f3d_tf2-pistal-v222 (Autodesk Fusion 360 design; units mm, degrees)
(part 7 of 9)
sketch "Sketch141" plane through (-0.0003, 0, 0) normal (-1, 0, 0) x axis (0, -1, 0)
  curve K1 (-134.7944, -30.1716) -> (-146.1998, -63.1046)
  curve K2 (-135.347, -29.366) -> (-134.7944, -30.1716)
  curve K3 (-136.1286, -29.6952) -> (-135.347, -29.366)
  line L1 (-136.7565, -29.9764) -> (-136.1286, -29.6952)
  line L2 (-136.8552, -29.6952) -> (-136.7565, -29.9764)
  line L3 (-144.3129, -29.6952) -> (-136.8552, -29.6952)
  line L4 (-159.3646, -64.9915) -> (-144.3129, -29.6952)
  line L5 (-144.2618, -68.8977) -> (-159.3646, -64.9915)
  curve K4 (-143.2922, -67.2348) -> (-144.2618, -68.8977)
  curve K5 (-143.2922, -67.2348) -> (-146.2332, -63.1316)
  line L6 (-147.5, -52.5) -> (-140.5, -52.5)
  line L7 (-147.5, -45.5) -> (-147.5, -52.5)
  line L8 (-140.5, -45.5) -> (-147.5, -45.5)
  line L9 (-140.5, -52.5) -> (-140.5, -45.5)
  line L10 (-147.5, -45.5) -> (-140.5, -52.5)
  line L11 (-140.5, -45.5) -> (-147.5, -52.5)
  arc A1 centre (-147.1582, -61.9508) radius 1.5 clockwise from (-146.1998, -63.1046) to (-146.2332, -63.1316)
  point P18 (-144, -49)
  point P16 (-147.5, -45.5)
  point P17 (-140.5, -45.5)
  point P15 (-147.5, -52.5)
  horizontal L6
  perpendicular L6 L7
  parallel L6 L8
  parallel L7 L9
  coincident L10 P18
  coincident L11 P18
  dimension "d1160" distance P16 P17 = 7
  dimension "d1161" distance P15 P16 = 7
extrude "Extrude141" add sketch "Sketch141" profile of L6 L7 L8 L9 along normal blind 4
combine "Combine131"
move_face "MoveFace228"
move_face "MoveFace229"
move_face "MoveFace230"
move_face "MoveFace231"
move_face "MoveFace232"
chamfer "Chamfer75" distance 0.4
move_face "MoveFace233"
move_face "MoveFace234"
sketch "Sketch142" plane through (13, 0, 0) normal (-1, 0, 0) x axis (0, -1, 0)
  line L1 (-223.8866, 10) -> (-223.8866, 17)
  line L2 (-215.8866, 10) -> (-223.8866, 10)
  line L3 (-227, -22) -> (-227, -14.8472)
  line L4 (-167.4832, -22) -> (-227, -22)
  line L5 (-157.3502, 10) -> (-167.4832, -22)
  line L6 (-157.3502, 17) -> (-157.3502, 10)
  line L7 (-223.8866, 17) -> (-157.3502, 17)
  arc A1 centre (-185.5, -18.5) radius 41.6604 clockwise from (-227, -14.8472) to (-215.8866, 10)
  circle C1 centre (-185.5706, -18.2123) radius 2.5
  arc A2 centre (-162.3398, -25.3102) radius 12.267 clockwise from (-154.6681, -15.7382) to (-155.8322, -35.7087)
  circle C2 centre (-162.3398, -25.3102) radius 19.545
  concentric A2 C2
extrude "Extrude142" new body sketch "Sketch142" profile of L4 L5 C2 against normal blind 5.398
mirror "Mirror33" mirrorStitchTolerance 0.1
combine "Combine132"
combine "Combine133"
move_face "MoveFace235"
fillet "Fillet164" radius 3.5
move_face "MoveFace236"
fillet "Fillet165" radius 3.5
extrude "Extrude143" cut of existing geometry blind -18
extrude "Extrude144" cut of existing geometry blind -29
offset_faces "OffsetFaces17" distance 0.8
sketch "Sketch143" plane through (-18.0019, 0, 0) normal (-1, 0, 0) x axis (0, -1, 0)
  line L1 (-163.0153, -60.3193) -> (-143.9303, -157.3483)
  line L2 (-163.931, -57.8793) -> (-163.0153, -60.3193)
  curve K1 (-163.8476, -56.0881) -> (-163.931, -57.8793)
  curve K2 (-163.8476, -56.0881) -> (-157.7262, -38.8106)
  curve K3 (-155.8322, -35.7087) -> (-157.7262, -38.8106)
  line L3 (-200.2987, -133.9094) -> (-171.9916, -32.8813)
  arc A1 centre (-162.3398, -25.3102) radius 133.3153 clockwise from (-143.9303, -157.3483) to (-186.1858, -156.4755)
  arc A2 centre (-162.3398, -25.3102) radius 12.267 clockwise from (-171.9916, -32.8813) to (-155.8322, -35.7087)
  arc A3 centre (-182.9662, -138.7658) radius 18 clockwise from (-186.1858, -156.4755) to (-200.2987, -133.9094)
  circle C1 centre (-162.4377, -25.1855) radius 2.7
extrude "Extrude145" cut sketch "Sketch143" profile of C1 against normal blind 4
sketch "Sketch144" plane through (17.9981, 0, 0) normal (1, 0, 0) x axis (0, 1, 0)
  line L1 (153.0202, 9.7517) -> (162.2233, -13.0438)
  line L2 (154.6681, -15.7382) -> (153.0202, 9.7517)
  curve K1 (155.8322, -35.7087) -> (163.931, -57.8793)
  line L3 (163.0153, -60.3193) -> (163.931, -57.8793)
  line L4 (143.9303, -157.3483) -> (163.0153, -60.3193)
  line L5 (171.9916, -32.8813) -> (200.2987, -133.9094)
  arc A1 centre (162.3398, -25.3102) radius 12.267 clockwise from (155.8322, -35.7087) to (154.6681, -15.7382)
  arc A2 centre (162.3398, -25.3102) radius 133.3153 clockwise from (186.1858, -156.4755) to (143.9303, -157.3483)
  arc A3 centre (182.9662, -138.7658) radius 18 clockwise from (200.2987, -133.9094) to (186.1858, -156.4755)
  arc A4 centre (162.3398, -25.3102) radius 12.267 clockwise from (162.2233, -13.0438) to (171.9916, -32.8813)
  circle C1 centre (162.4377, -25.1855) radius 2.7
extrude "Extrude146" cut sketch "Sketch144" profile of C1 against normal blind 4
sketch "Sketch145" plane through (13.9981, 0, 0) normal (1, 0, 0) x axis (0, 1, 0)
  circle C1 centre (162.4377, -25.1855) radius 2.7
  circle C2 centre (162.4377, -25.1855) radius 2.5
  concentric C1 C2
  dimension "d1182" diameter C2 = 5
extrude "Extrude147" new body sketch "Sketch145" profile of C2 along normal blind 8 bodies "Trigger pin 1"
mirror "Mirror34" mirrorStitchTolerance 0.1 bodies "Trigger pin 2"
sketch "Sketch146" plane through (0, 0, 0) normal (-1, 0, 0) x axis (0, -1, 0)
  line L1 (-221.138, -55.0188) -> (-226.6232, -53.5432)
  line L2 (-220.3025, -51.9132) -> (-221.138, -55.0188)
  line L3 (-219.9103, -50.4552) -> (-220.3025, -51.9132)
  line L4 (-221, -47) -> (-219.9103, -50.4552)
  line L5 (-228.6991, -19.812) -> (-221, -47)
  line L6 (-249.5886, -19.812) -> (-228.6991, -19.812)
  line L7 (-235.4799, -32.5465) -> (-249.5886, -19.812)
  line L8 (-232.2172, -48.7291) -> (-232.2172, -34.9278)
  curve K1 (-233.7172, -53.9969) -> (-232.2172, -48.7291)
  curve K2 (-234.0863, -54.5504) -> (-233.7172, -53.9969)
  curve K3 (-274.1373, -137.1288) -> (-234.0863, -54.5504)
  line L9 (-262.8717, -140.8736) -> (-274.1373, -137.1288)
  line L10 (-259.7804, -131.5739) -> (-262.8717, -140.8736)
  line L11 (-243.214, -137.0808) -> (-259.7804, -131.5739)
  line L12 (-225.7243, -72.0674) -> (-243.214, -137.0808)
  line L13 (-225.1962, -70.1041) -> (-225.7243, -72.0674)
  line L14 (-230.9458, -56.7232) -> (-225.1962, -70.1041)
  line L15 (-228.7303, -48.4876) -> (-230.9458, -56.7232)
  line L16 (-225.4972, -49.3573) -> (-228.7303, -48.4876)
  line L17 (-226.6232, -53.5432) -> (-225.4972, -49.3573)
  line L18 (-248.9379, -95.078) -> (-240, -75)
  line L19 (-240, -99.0568) -> (-248.9379, -95.078)
  line L20 (-231.8266, -74.6064) -> (-242.2626, -98.0496)
  line L21 (-233.3246, -77.9716) -> (-240, -75)
  line L22 (-271.4894, -85.039) -> (-248.9379, -95.078)
  line L23 (-259.8634, -66.1576) -> (-240, -75)
  arc A1 centre (-222.4144, -18.0709) radius 19.5 clockwise from (-232.2172, -34.9278) to (-235.4799, -32.5465)
  point P27 (-242.2626, -98.0496)
  point P29 (-233.3246, -77.9716)
  perpendicular L18 L19
  coincident L19 P27
  perpendicular L19 L20
  coincident L20 P29
  perpendicular L20 L21
  perpendicular L18 L22
  perpendicular L18 L23
extrude "Extrude148" new body sketch "Sketch146" profile of K3 L18 L22 L23 along normal blind 5
extrude "Extrude149" new body sketch "Sketch146" profile of L18 L19 L20 L21 against normal blind 5
combine "Combine134"
combine "Combine135"
combine "Combine136"
combine "Combine137"
move_face "MoveFace237"
move_face "MoveFace238"
delete_face "DeleteFace132"
move_face "MoveFace239"
move_face "MoveFace240"
move_face "MoveFace241"
move_face "MoveFace242"
move_face "MoveFace243"
move_face "MoveFace244"
move_face "MoveFace245"
sketch "Sketch147" plane through (0, 172.4408, 76.7638) normal (0, 0.9136, 0.4067) x axis (-1, 0, 0)
  line L1 (5, -166.1219) -> (5, -180.0994)
  line L2 (0, -166.1219) -> (5, -166.1219)
  line L3 (0, -166.3219) -> (0, -166.1219)
  line L4 (-4.8, -166.3219) -> (0, -166.3219)
  line L5 (-4.8, -179.8994) -> (-4.8, -166.3219)
  line L6 (0, -179.8994) -> (-4.8, -179.8994)
  line L7 (0, -180.0994) -> (0, -179.8994)
  line L8 (5, -180.0994) -> (0, -180.0994)
  circle C1 centre (0, -173) radius 1.55
  dimension "d1191" diameter C1 = 3.1
extrude "Extrude150" cut sketch "Sketch147" profile of C1 along normal blind 11 and against normal blind 4
sketch "Sketch148" plane through (0, 172.6236, 76.8451) normal (0, -0.9136, -0.4067) x axis (1, 0, 0)
  line L1 (5, -166.1219) -> (5, -180.0994)
  line L2 (0, -166.1219) -> (5, -166.1219)
  line L3 (0, -166.3219) -> (0, -166.1219)
  line L4 (-5, -166.3219) -> (0, -166.3219)
  line L5 (-5, -179.8994) -> (-5, -166.3219)
  line L6 (0, -179.8994) -> (-5, -179.8994)
  line L7 (0, -180.0994) -> (0, -179.8994)
  line L8 (5, -180.0994) -> (0, -180.0994)
  circle C1 centre (0, -173) radius 1.55
  circle C2 centre (0, -173) radius 3.1
  concentric C1 C2
  dimension "d1196" diameter C2 = 6.2
extrude "Extrude151" cut sketch "Sketch148" profile of C1 C2 blind -6 from offset -4
chamfer "Chamfer76" distance 1.4
move_face "MoveFace246"
sketch "Sketch149" plane through (-21.9977, 0, 0) normal (-1, 0, 0) x axis (0, -1, 0)
  line L1 (-251.5226, -138.0193) -> (-252.4999, -140.9593)
  line L2 (-250.6312, -137.5727) -> (-251.5226, -138.0193)
  line L3 (-246.3705, -138.989) -> (-250.6312, -137.5727)
  line L4 (-245.9238, -139.8804) -> (-246.3705, -138.989)
  line L5 (-246.9532, -142.977) -> (-245.9238, -139.8804)
  line L6 (-202.4935, -157.7558) -> (-246.9532, -142.977)
  line L7 (-197.128, -152.3541) -> (-198.032, -155.4234)
  line L8 (-197.128, -141.3784) -> (-197.128, -152.3541)
  line L9 (-157.1727, -23.4112) -> (-197.128, -141.3784)
  line L10 (-181.4232, -15.4864) -> (-162.8556, -15.4864)
  line L11 (-182.8566, -22.0495) -> (-181.4232, -15.4864)
  line L12 (-220.8838, -26.6905) -> (-188.6207, -26.6905)
  line L13 (-220.8838, -56.1363) -> (-220.8838, -26.6905)
  line L14 (-253.6825, -136.8114) -> (-220.8838, -56.1363)
  line L15 (-223, -24) -> (-222.607, -35.9739)
  line L16 (-212.2901, -25.397) -> (-223, -24)
  circle C1 centre (-162.4377, -25.1855) radius 2.7
  circle C2 centre (-210.9636, -95.9994) radius 18.6716
  arc A1 centre (-201.3894, -154.4345) radius 3.5 clockwise from (-198.032, -155.4234) to (-202.4935, -157.7558)
  arc A2 centre (-162.8556, -21.4864) radius 6 clockwise from (-162.8556, -15.4864) to (-157.1727, -23.4112)
  arc A3 centre (-188.6207, -20.7905) radius 5.9 clockwise from (-182.8566, -22.0495) to (-188.6207, -26.6905)
  arc A4 centre (-250.4402, -138.1296) radius 3.5 clockwise from (-252.4999, -140.9593) to (-253.6825, -136.8114)
  arc A5 centre (-212, -36) radius 10.607 clockwise from (-222.607, -35.9739) to (-212.2901, -25.397)
extrude "Extrude152" cut sketch "Sketch149" profile of L12 L13 A5 L15 L16 against normal blind 2
fillet "Fillet166" radius 0.7
move_face "MoveFace247"
sketch "Sketch150" plane through (-19.9977, 0, 0) normal (-1, 0, 0) x axis (0, -1, 0)
  line L1 (-246.6184, -139.2754) -> (-250.604, -137.9506)
  line L2 (-246.3017, -139.9076) -> (-246.6184, -139.2754)
  line L3 (-247.6265, -143.8932) -> (-246.3017, -139.9076)
  line L4 (-248.2587, -144.2099) -> (-247.6265, -143.8932)
  line L5 (-252.2443, -142.8851) -> (-248.2587, -144.2099)
  line L6 (-252.5611, -142.2529) -> (-252.2443, -142.8851)
  line L7 (-251.2362, -138.2673) -> (-252.5611, -142.2529)
  line L8 (-250.604, -137.9506) -> (-251.2362, -138.2673)
  line L9 (-153.2868, -55.2709) -> (-155.774, -64.8873)
  curve K1 (-153.2868, -55.2709) -> (-153.3896, -51.2349)
  line L10 (-153.3078, -51.0336) -> (-153.3896, -51.2349)
  line L11 (-209.4603, -30.1452) -> (-144.1511, -30.1452)
  curve K2 (-209.4603, -30.1452) -> (-209.6429, -30.1443)
  line L12 (-255.6377, -143.2782) -> (-209.6429, -30.1443)
  line L13 (-209.1721, -158.7239) -> (-255.6377, -143.2782)
  line L14 (-185.0159, -86.0541) -> (-209.1721, -158.7239)
  line L15 (-158.6388, -64.1463) -> (-159.119, -65.3274)
  line L16 (-155.774, -64.8873) -> (-158.6388, -64.1463)
  arc A1 centre (-116.7403, -54.6121) radius 36.7422 clockwise from (-153.3078, -51.0336) to (-144.1511, -30.1452)
  arc A2 centre (-156.0731, -95.675) radius 30.5 clockwise from (-185.0159, -86.0541) to (-159.119, -65.3274)
  circle C1 centre (-205, -40) radius 2.6
  dimension "d1205" diameter C1 = 5.2
extrude "Extrude153" new body sketch "Sketch150" profile of C1 along normal blind 4 and against normal blind 4 bodies "5mm pin_3"
combine "Combine138"
remove_body "RemoveBody80"
combine "Combine139"
combine "Combine140"
mirror "Mirror35" mirrorStitchTolerance 0.1 bodies "5mm pin_4"
combine "Combine141"
combine "Combine142"
mirror "Mirror36" mirrorStitchTolerance 0.1 bodies "Grip plate_L"
offset_faces "OffsetFaces18" distance -0.1
offset_faces "OffsetFaces19" distance -0.1
move_face "MoveFace248"
move_face "MoveFace249"
delete_face "DeleteFace133"
delete_face "DeleteFace134"
move_face "MoveFace250" TranslateX 0 TranslateY 0.5 TranslateZ 0
sketch "Sketch151" plane through (0, 70.058, 0) normal (0, 1, 0) x axis (-1, 0, 0)
  line L1 (8.4524, 1) -> (8.4524, 26)
  line L2 (15.2981, 1) -> (8.4524, 1)
  line L3 (15.2981, -14.4738) -> (15.2981, 1)
  line L4 (-7.5981, -22.1738) -> (7.5981, -22.1738)
  line L5 (-15.2981, 1) -> (-15.2981, -14.4738)
  line L6 (-8.4524, 1) -> (-15.2981, 1)
  line L7 (-8.4524, 26) -> (-8.4524, 1)
  line L8 (8.4524, 26) -> (-8.4524, 26)
  line L9 (-1.9977, 30) -> (1.9973, 30)
  line L10 (-17.9977, 14) -> (-19.6612, 14)
  line L11 (-17.9977, 10) -> (-17.9977, 14)
  line L12 (-18.3981, 10) -> (-17.9977, 10)
  line L13 (-18.3981, 1) -> (-18.3981, 10)
  line L14 (-15.4981, 1) -> (-18.3981, 1)
  line L15 (-15.4981, -24.564) -> (-15.4981, 1)
  line L16 (-15.4981, -24.564) -> (15.4981, -24.564)
  line L17 (15.4981, 1) -> (15.4981, -24.564)
  line L18 (18.3981, 1) -> (15.4981, 1)
  line L19 (18.3981, 10) -> (18.3981, 1)
  line L20 (17.9977, 10) -> (18.3981, 10)
  line L21 (17.9977, 14) -> (17.9977, 10)
  line L22 (19.6609, 14) -> (17.9977, 14)
  line L23 (-12.5, -22.064) -> (-17.5, -22.064)
  line L24 (-12.5, -27) -> (-12.5, -22.064)
  line L25 (-17.5, -27) -> (-12.5, -27)
  line L26 (-17.5, -22.064) -> (-17.5, -27)
  circle C1 centre (15.0846, 20.3468) radius 2
  circle C2 centre (-15.0846, 20.3468) radius 2
  arc A1 centre (7.5981, -14.4738) radius 7.7 clockwise from (15.2981, -14.4738) to (7.5981, -22.1738)
  arc A2 centre (-7.5981, -14.4738) radius 7.7 clockwise from (-7.5981, -22.1738) to (-15.2981, -14.4738)
  arc A3 centre (19.6609, 14.2) radius 0.2 clockwise from (19.8593, 14.2247) to (19.6609, 14)
  arc A4 centre (1.9973, 12) radius 18 clockwise from (1.9973, 30) to (19.8593, 14.2247)
  arc A5 centre (-1.9977, 12) radius 18 clockwise from (-19.8597, 14.2247) to (-1.9977, 30)
  arc A6 centre (-19.6612, 14.2) radius 0.2 clockwise from (-19.6612, 14) to (-19.8597, 14.2247)
  circle C3 centre (-15, -22.064) radius 2.5
  point P39 (-17.5, -22.064)
  tangent L16 C3
  horizontal L23
  vertical L24
  horizontal L25
  vertical L26
  coincident C3 P39
  dimension "d1219" diameter C3 = 5
extrude "Extrude154" new body sketch "Sketch151" profile of L15 L16 C3 L23 L24 L25 L26 along normal blind 2 and against normal blind 0
sweep "Sweep1" TwistAngle 0 TaperAngle 0
combine "Combine143"
mirror "Mirror37" mirrorStitchTolerance 0.1
move "Move87" TranslateX 10 TranslateY 0 TranslateZ 0
move "Move88" TranslateX -12 TranslateY 0 TranslateZ 0
move "Move89" TranslateX 2.5 TranslateY 0 TranslateZ 0
move "Move90" TranslateX -0.5 TranslateY 0 TranslateZ 0
move "Move91" TranslateX 0 TranslateY 0.5 TranslateZ 0.5
move "Move92" TranslateX 0 TranslateY 0 TranslateZ -0.5
combine "Combine144"
fillet "Fillet167" radius 0.5
sketch "Sketch152" plane through (19.9977, 0, 0) normal (1, 0, 0) x axis (0, 1, 0)
  line L1 (34.1807, 10) -> (104.3129, 10)
  line L2 (21.5097, 10) -> (34.1807, 10)
  line L3 (21.5097, -1.9634) -> (21.5097, 10)
  curve K1 (21.5097, -1.9634) -> (21.9053, -3.4061)
  curve K2 (21.9053, -3.4061) -> (75.0239, -22.5858)
  line L4 (104.3129, -22.5858) -> (75.0239, -22.5858)
  line L5 (104.3129, 10) -> (104.3129, -22.5858)
  line L6 (13, -4) -> (21, -14)
  line L7 (9, -9) -> (13, -4)
  line L8 (15.5914, -17.2392) -> (9, -9)
  line L9 (21, -14) -> (15.5914, -17.2392)
  parallel L6 L8
extrude "Extrude155" new body sketch "Sketch152" profile of L6 L7 L8 L9 against normal blind 15
sketch "Sketch153" plane through (0, 5.9756, 4.7805) normal (0, 0.7809, 0.6247) x axis (-1, 0, 0)
  line L1 (-19.9977, -24.0508) -> (-19.9977, -11.2445)
  line L2 (-4.9977, -24.0508) -> (-19.9977, -24.0508)
  line L3 (-4.9977, -11.2445) -> (-4.9977, -24.0508)
  line L4 (-19.9977, -11.2445) -> (-4.9977, -11.2445)
  circle C1 centre (0, -24) radius 6
extrude "Extrude156" cut sketch "Sketch153" profile of L2 L3 C1 along normal blind 10
fillet "Fillet168" radius 0.5
sketch "Sketch154" plane through (0, 13.7843, 11.0274) normal (0, -0.7809, -0.6247) x axis (1, 0, 0)
  line L1 (-0.9759, -22.8753) -> (-0.971, -22.9146)
  curve K1 (-0.971, -22.9146) -> (-0.789, -24.1633)
  curve K2 (-0.789, -24.1633) -> (0, -28.7793)
  curve K3 (0, -28.7793) -> (0.789, -24.1633)
  curve K4 (0.789, -24.1634) -> (0.971, -22.9146)
  line L2 (0.971, -22.9146) -> (0.9759, -22.8753)
  curve K5 (0.9759, -22.8753) -> (4.0241, -22.8753)
  line L3 (4.0241, -22.8753) -> (4.029, -22.9146)
  curve K6 (4.029, -22.9146) -> (4.211, -24.1633)
  curve K7 (4.211, -24.1633) -> (4.8061, -27.5918)
  curve K8 (-4.8061, -27.5918) -> (-4.211, -24.1634)
  curve K9 (-4.211, -24.1634) -> (-4.029, -22.9146)
  line L4 (-4.029, -22.9146) -> (-4.0241, -22.8753)
  curve K10 (-4.0241, -22.8753) -> (-0.9759, -22.8753)
  arc A1 centre (0, -24) radius 6 clockwise from (-4.8061, -27.5918) to (4.8061, -27.5918)
  circle C1 centre (0, -24) radius 1.75
  concentric A1 C1
  dimension "d1258" diameter C1 = 3.5
extrude "Extrude157" cut sketch "Sketch154" profile of L1 K1 K2 K3 K4 L2 K5 K10 C1 against normal blind 6
fillet "Fillet169" radius 0.5
remove_body "RemoveBody81"
offset_faces "OffsetFaces20" distance 0.1
offset_faces "OffsetFaces21" distance 0.05
offset_faces "OffsetFaces22" distance 0.05
offset_faces "OffsetFaces23" distance 0.05
fillet "Fillet170" radius 0.5
sketch "Sketch155" plane through (0, 18.4695, 14.7756) normal (0, -0.7809, -0.6247) x axis (1, 0, 0)
  circle C1 centre (0, -24) radius 1.75
  circle C2 centre (0, -24) radius 1.4
  concentric C1 C2
  dimension "d1269" diameter C2 = 2.8
extrude "Extrude158" add sketch "Sketch155" along normal blind 6
chamfer "Chamfer77" distance 0.3
offset_faces "OffsetFaces24" distance -0.1
offset_faces "OffsetFaces25" distance -0.1
sketch "Sketch156" plane through (17.9981, 0, 0) normal (1, 0, 0) x axis (0, 1, 0)
  line L1 (153.0202, 9.7517) -> (162.2233, -13.0438)
  line L2 (154.6681, -15.7382) -> (153.0202, 9.7517)
  curve K1 (155.8322, -35.7087) -> (163.931, -57.8793)
  line L3 (163.0153, -60.3193) -> (163.931, -57.8793)
  line L4 (143.9303, -157.3483) -> (163.0153, -60.3193)
  line L5 (171.9916, -32.8813) -> (200.2987, -133.9094)
  line L6 (149.2123, -50.8939) -> (147, -52)
  line L7 (191.6889, -41.9084) -> (149.2123, -50.8939)
  line L8 (201, -46) -> (149, -57)
  line L9 (165.0095, -53.6134) -> (165.0095, -47.5521)
  line L10 (175, -51.5) -> (171.7876, -46.1183)
  line L11 (165.2595, -53.5605) -> (165.2595, -47.4992)
  line L12 (174.7415, -51.5547) -> (171.5291, -46.173)
  line L13 (182.7307, -44.059) -> (150.4604, -50.8854)
  line L14 (151.6826, -50.6268) -> (151.6309, -50.3822)
  line L15 (181.5745, -44.3035) -> (181.5227, -44.059)
  line L16 (160.5395, -54.3034) -> (160.2764, -54.3034)
  line L17 (182.4377, -49.6711) -> (160.5395, -54.3034)
  line L18 (161.3682, -54.3836) -> (161.3165, -54.1391)
  line L19 (181.323, -50.1624) -> (181.2713, -49.9179)
  circle C1 centre (162.4377, -25.1855) radius 2.7
  arc A1 centre (162.3398, -25.3102) radius 12.267 clockwise from (155.8322, -35.7087) to (154.6681, -15.7382)
  arc A2 centre (162.3398, -25.3102) radius 133.3153 clockwise from (186.1858, -156.4755) to (143.9303, -157.3483)
  arc A3 centre (182.9662, -138.7658) radius 18 clockwise from (200.2987, -133.9094) to (186.1858, -156.4755)
  arc A4 centre (162.3398, -25.3102) radius 12.267 clockwise from (162.2233, -13.0438) to (171.9916, -32.8813)
  point P20 (165.0095, -47.5521)
  point P21 (165.0095, -53.6134)
  point P22 (171.7876, -46.1183)
  point P23 (175, -51.5)
  point P24 (165.2595, -47.4992)
  point P25 (165.2595, -53.5605)
  point P26 (171.5291, -46.173)
  point P27 (174.7415, -51.5547)
  point P30 (151.6309, -50.3822)
  point P31 (151.6826, -50.6268)
  point P32 (181.5227, -44.059)
  point P33 (181.5745, -44.3035)
  point P37 (161.3165, -54.1391)
  point P38 (161.3682, -54.3836)
  point P39 (181.2713, -49.9179)
  point P40 (181.323, -50.1624)
  parallel L7 L8
  coincident L7 P20
  coincident L8 P21
  vertical L9
  coincident L7 P22
  midpoint L8 P23
  coincident L7 P24
  coincident L8 P25
  vertical L11
  coincident L7 P26
  coincident L8 P27
  parallel L7 L13
  parallel L10 L12
  coincident L7 P30
  coincident L13 P31
  perpendicular L13 L14
  coincident L7 P32
  coincident L13 P33
  perpendicular L13 L15
  perpendicular L9 L16
  parallel L8 L17
  coincident L17 P37
  coincident L8 P38
  perpendicular L8 L18
  coincident L17 P39
  coincident L8 P40
  perpendicular L8 L19
  dimension "d1275" distance L7 L13 = 0.25
  dimension "d1276" distance L9 L11 = 0.25
  dimension "d1277" distance L10 L12 = 0.25
  dimension "d1283" distance L8 L17 = 0.25
sketch "Sketch157" plane through (17.9981, 0, 0) normal (1, 0, 0) x axis (0, 1, 0)
  line L1 (156.0354, -13.7107) -> (151.0894, -15.2814)
  line L2 (157.9379, -19.7019) -> (156.0354, -13.7107)
  line L3 (161.5785, -18.5458) -> (157.9379, -19.7019)
  line L4 (159.6732, -12.5461) -> (161.5785, -18.5458)
  line L5 (166.5717, -10.3554) -> (159.6732, -12.5461)
  line L6 (166.6474, -10.5937) -> (166.5717, -10.3554)
  line L7 (159.9872, -12.7087) -> (166.6474, -10.5937)
  line L8 (161.8924, -18.7084) -> (159.9872, -12.7087)
  line L9 (157.7753, -20.0158) -> (161.8924, -18.7084)
  line L10 (155.8727, -14.0247) -> (157.7753, -20.0158)
  line L11 (147.3025, -16.7463) -> (155.8727, -14.0247)
  line L12 (151.165, -15.5197) -> (151.0894, -15.2814)
  point P14 (151.165, -15.5197)
  perpendicular L1 L2
  perpendicular L2 L3
  perpendicular L3 L4
  perpendicular L4 L5
  perpendicular L5 L6
  perpendicular L6 L7
  perpendicular L7 L8
  perpendicular L8 L9
  perpendicular L9 L10
  perpendicular L10 L11
  coincident L11 P14
  perpendicular L11 L12
  dimension "d1278" distance L1 L11 = 0.25
  dimension "d1279" distance L2 L10 = 0.25
  dimension "d1280" distance L3 L9 = 0.25
  dimension "d1281" distance L4 L8 = 0.25
  dimension "d1282" distance L5 L7 = 0.25
extrude "Extrude159" cut sketch "Sketch157" + "Sketch156" profile of S2:K1 S2:L5 S2:L7 S2:L8 S2:L9 S2:L10 S2:L11 S2:L12 S2:L13 S1:L1 S1:L2 S1:L3 S1:L4 S1:L5 S1:L6 S1:L7 S1:L8 S1:L9 S1:L10 S1:L11 S1:L12 S2:L14 S2:L15 S2:L17 blind -5 bodies "Trigger_Gear_L", "Trigger(OG)"
split "Split54" bodies "Trigger"
mirror "Mirror38" mirrorStitchTolerance 0.1 bodies "Trigger_Pic_R", "Trigger_Gear_R", "Trigger (2) (1) (1)"
combine "Combine145" bodies "Trigger (2) (1) (1)"
sketch "Sketch158" plane through (0, 0.595, -10.1995) normal (0, -0.0582, 0.9983) x axis (1, 0, 0)
  line L1 (8.0049, 214.6381) -> (-8.0049, 214.6381)
  line L2 (8.0049, 227.9303) -> (8.0049, 214.6381)
  line L3 (8.0049, 227.9303) -> (-8.0049, 227.9303)
  line L4 (-8.0049, 214.6381) -> (-8.0049, 227.9303)
  circle C1 centre (0, 221.2842) radius 2.5
  dimension "d1288" diameter C1 = 5
extrude "Extrude160" cut sketch "Sketch158" profile of C1 against normal blind 4.947
sketch "Sketch159" plane through (0, 0, -10.9038) normal (0, 0, 1) x axis (-1, 0, 0)
  line L1 (0, -220.9739) -> (0, -247.6613)
  line L2 (-8.7952, -220.9739) -> (0, -220.9739)
  line L3 (-8.7952, -243.8316) -> (-8.7952, -220.9739)
  line L4 (-17.6329, -243.8316) -> (-8.7952, -243.8316)
  line L5 (-20.9977, -226.9157) -> (-17.6329, -243.8316)
  line L6 (-20.9977, -189.3316) -> (-20.9977, -226.9157)
  line L7 (-23.9972, -189.3316) -> (-20.9977, -189.3316)
  line L8 (-23.9972, -223.6753) -> (-23.9972, -189.3316)
  line L9 (-19.2261, -247.6613) -> (-23.9972, -223.6753)
  line L10 (0, -247.6613) -> (-19.2261, -247.6613)
  circle C1 centre (-4, -222) radius 1.5
  circle C2 centre (4, -222) radius 1.5
  dimension "d1291" diameter C1 = 3
  dimension "d1292" diameter C2 = 3
extrude "Extrude161" cut sketch "Sketch159" profile of L2 C1 C2 against normal blind 12
delete_face "DeleteFace135"
sketch "Sketch160" plane through (0, 0.595, -10.1995) normal (0, -0.0582, 0.9983) x axis (1, 0, 0)
  line L1 (8.0049, 214.6381) -> (-8.0049, 214.6381)
  line L2 (8.0049, 227.9303) -> (8.0049, 214.6381)
  line L3 (8.0049, 227.9303) -> (-8.0049, 227.9303)
  line L4 (-8.0049, 214.6381) -> (-8.0049, 227.9303)
  curve K1 (2.9058, 219.9639) -> (5.0942, 219.9639)
  curve K2 (5.4998, 220.4703) -> (2.5002, 220.4703)
  curve K3 (-5.0942, 219.9639) -> (-2.9058, 219.9639)
  curve K4 (-2.5002, 220.4703) -> (-5.4998, 220.4703)
  closed curve K5 centre (4, 220.4932)
  closed curve K6 centre (-4, 220.4932)
extrude "Extrude162" cut sketch "Sketch160" profile of K2 K5 K4 K6 against normal blind 4.947
fillet "Fillet171" radius 1
sketch "Sketch161" plane through (19.9977, 0, 0) normal (1, 0, 0) x axis (0, 1, 0)
  line L1 (34.1807, 10) -> (104.3129, 10)
  line L2 (21.5097, 10) -> (34.1807, 10)
  line L3 (21.5097, -1.9634) -> (21.5097, 10)
  curve K1 (21.5097, -1.9634) -> (21.9053, -3.4061)
  curve K2 (21.9053, -3.4061) -> (75.0239, -22.5858)
  line L4 (104.3129, -22.5858) -> (75.0239, -22.5858)
  line L5 (104.3129, 10) -> (104.3129, -22.5858)
  curve K3 (20.0402, -4.4195) -> (71.4649, -24.6227)
  curve K4 (21.9053, -3.4061) -> (75.0239, -22.5858)
  line L6 (20.0402, -4.4195) -> (21.9053, -3.4061)
  line L7 (74.9876, -24.7216) -> (71.4649, -24.6227)
  line L8 (75.0239, -22.5858) -> (74.9876, -24.7216)
  point P12 (21.9053, -3.4061)
  point P13 (21.9053, -3.4061)
  point P10 (20.0402, -4.4195)
  point P14 (20.0402, -4.4195)
  point P9 (71.4649, -24.6227)
  point P15 (71.4649, -24.6227)
  point P11 (75.0239, -22.5858)
  point P17 (75.0239, -22.5858)
  coincident P12 P13
  coincident P10 P14
  coincident P9 P15
  coincident P11 P17
extrude "Extrude163" new body sketch "Sketch161" profile of K2 K3 K4 L6 L7 L8 along normal blind 16
move "Move93"
move_face "MoveFace251"
move_face "MoveFace252"
combine "Combine146"
sketch "Sketch162" plane through (0, 13.7843, 11.0274) normal (0, -0.7809, -0.6247) x axis (1, 0, 0)
  curve K1 (-0.5315, -25.6673) -> (0, -28.7793)
  curve K2 (0, -28.7793) -> (0.5315, -25.6673)
  curve K3 (1.1129, -22.6495) -> (4.0241, -22.8753)
  line L1 (4.0241, -22.8753) -> (4.029, -22.9146)
  curve K4 (4.029, -22.9146) -> (4.211, -24.1633)
  curve K5 (4.211, -24.1633) -> (4.8061, -27.5918)
  curve K6 (-4.8061, -27.5918) -> (-4.211, -24.1634)
  curve K7 (-4.211, -24.1634) -> (-4.029, -22.9146)
  line L2 (-4.029, -22.9146) -> (-4.0241, -22.8753)
  curve K8 (-4.0241, -22.8753) -> (-1.1129, -22.6495)
  arc A1 centre (0, -24) radius 1.75 clockwise from (1.1129, -22.6495) to (0.5315, -25.6673)
  arc A2 centre (0, -24) radius 6 clockwise from (-4.8061, -27.5918) to (4.8061, -27.5918)
  arc A3 centre (0, -24) radius 1.75 clockwise from (-0.5315, -25.6673) to (-1.1129, -22.6495)
  circle C1 centre (0, -24) radius 1.7
  circle C2 centre (0, -24) radius 1.4
  circle C3 centre (0, -24) radius 1.4
extrude "Extrude164" cut sketch "Sketch162" profile of C2 C3 along normal blind 31
chamfer "Chamfer78" distance 1.4
move "Move94"
move "Move95"
move_face "MoveFace253"
move_face "MoveFace254"
move_face "MoveFace255"
move_face "MoveFace256"
move "Move96"
sketch "Sketch163" plane through (0, 151.3741, 0) normal (0, -1, 0) x axis (1, 0, 0)
  curve K1 (4.1878, 21.505) -> (4.1878, 21.505)
  line L1 (-5.5, 15) -> (5.5, 15)
  line L2 (-5.5, 10.6856) -> (-5.5, 15)
  line L3 (5.5, 10.6856) -> (-5.5, 10.6856)
  line L4 (5.5, 15) -> (5.5, 10.6856)
  line L5 (-5.5, 10.6856) -> (5.5, 15)
  line L6 (5.5, 10.6856) -> (-5.5, 15)
  line L7 (4.5721, 21.8707) -> (4.5729, 21.8698)
  curve K2 (4.5729, 21.8698) -> (4.5721, 21.8707)
  line L8 (4.8831, 22.1897) -> (4.5721, 21.8707)
  line L9 (4.5721, 21.8707) -> (4.8831, 22.1897)
  line L10 (6.5, 15) -> (-6.6877, 15)
  arc A1 centre (0, 17.5648) radius 6.7256 clockwise from (-6.338, 19.8148) to (4.8831, 22.1897)
  arc A2 centre (0, 17.5648) radius 6.7256 clockwise from (6.3384, 19.814) to (-6.338, 19.8148)
  arc A3 centre (0, 17.5648) radius 6.7256 clockwise from (4.8831, 22.1897) to (6.3384, 19.814)
  point P8 (0, 12.8428)
  horizontal L1
  perpendicular L1 L2
  parallel L1 L3
  parallel L2 L4
  coincident L5 P8
  coincident L6 P8
  perpendicular L4 L10
extrude "Extrude165" cut sketch "Sketch163" profile of K1 L1 L2 L4 K2 A2 L10 against normal blind 3
move_face "MoveFace257" RotateAngle -20
move_face "MoveFace258" TranslateX 0 TranslateY 0 TranslateZ -1.5
move_face "MoveFace259" RotateAngle -5
fillet "Fillet172" radius 0.5
fillet "Fillet173" radius 1.75
fillet "Fillet174" radius 0.25
move_face "MoveFace260" TranslateX 2.002 TranslateY 0 TranslateZ 0
move_face "MoveFace261" TranslateX -0.0001 (= "-8.083E-05 mm") TranslateY 0 TranslateZ 0
move_face "MoveFace262" TranslateX -2.002 TranslateY 0 TranslateZ 0
move_face "MoveFace263" TranslateX 0.0001 (= "8.083E-05 mm") TranslateY 0 TranslateZ 0
sketch "Sketch164" plane through (-13, 0, 0) normal (1, 0, 0) x axis (0, 1, 0)
  line L1 (226.9436, -21.8684) -> (184.2991, -21.8684)
  line L2 (226.9436, -14.7156) -> (226.9436, -21.8684)
  line L3 (223.8301, 10.1316) -> (215.8301, 10.1316)
  line L4 (223.8301, 17.1316) -> (223.8301, 10.1316)
  line L5 (157.2938, 17.1316) -> (223.8301, 17.1316)
  line L6 (157.2938, 10.1316) -> (157.2938, 17.1316)
  line L7 (162.2859, -5.6336) -> (157.2938, 10.1316)
  arc A1 centre (184.2991, -18.3684) radius 3.5 clockwise from (184.2991, -21.8684) to (180.9554, -19.4027)
  arc A2 centre (185.4436, -18.3684) radius 41.6604 clockwise from (215.8301, 10.1316) to (226.9436, -14.7156)
  arc A3 centre (162.2833, -25.1786) radius 19.545 clockwise from (162.2859, -5.6336) to (180.9554, -19.4027)
  circle C1 centre (185.5706, -18.2123) radius 2.5
  circle C2 centre (185.5706, -18.2123) radius 2.5
  circle C3 centre (185.5706, -18.2123) radius 7.1382
  concentric C1 C3
extrude "Extrude166" new body sketch "Sketch164" profile of A1 L1 A3 C1 C2 C3 against normal blind 5.398
move_face "MoveFace264" TranslateX 0.202 TranslateY 0 TranslateZ 0
mirror "Mirror39" mirrorStitchTolerance 0.1
move "Move97" TranslateX 1.6 TranslateY 0 TranslateZ 0
move "Move98" TranslateX -1.6 TranslateY 0 TranslateZ 0
offset_faces "OffsetFaces26" distance 1.5
combine "Combine147"
combine "Combine148"
sketch "Sketch165" plane through (16.798, 0, 0) normal (-1, 0, 0) x axis (0, -1, 0)
  line L1 (-184.2991, -21.8684) -> (-193.3969, -21.8684)
  arc A1 centre (-184.2991, -18.3684) radius 3.5 clockwise from (-180.9554, -19.4027) to (-184.2991, -21.8684)
  arc A2 centre (-162.2833, -25.1786) radius 19.545 clockwise from (-180.9554, -19.4027) to (-178.1581, -13.7769)
  arc A3 centre (-185.5706, -18.2123) radius 8.6382 clockwise from (-193.3969, -21.8684) to (-178.1581, -13.7769)
  circle C1 centre (-185.5706, -18.2123) radius 2.5
  circle C2 centre (-185.5706, -18.2123) radius 2.5
  circle C3 centre (-185.5706, -18.2123) radius 2.4
  concentric A3 C3
  dimension "d1343" diameter C3 = 4.8
extrude "Extrude167" new body sketch "Sketch165" profile of C3 along normal blind 7
sketch "Sketch166" plane through (19.9977, 0, 0) normal (1, 0, 0) x axis (0, 1, 0)
  line L1 (109.4436, -20.0755) -> (110.7365, -21.3684)
  line L2 (109.4436, -11.6613) -> (109.4436, -20.0755)
  line L3 (110.7365, -10.3684) -> (109.4436, -11.6613)
  line L4 (119.1507, -10.3684) -> (110.7365, -10.3684)
  line L5 (120.4436, -11.6613) -> (119.1507, -10.3684)
  line L6 (120.4436, -20.0755) -> (120.4436, -11.6613)
  line L7 (119.1507, -21.3684) -> (120.4436, -20.0755)
  line L8 (110.7365, -21.3684) -> (119.1507, -21.3684)
  curve K1 (108.2303, -22.4542) -> (115.4874, -24.8684)
  line L9 (121.1997, -24.8684) -> (115.4874, -24.8684)
  curve K2 (140.7309, -29.1136) -> (121.1997, -24.8684)
  line L10 (210.1276, -29.1136) -> (140.7309, -29.1136)
  line L11 (227.5323, -71.9239) -> (210.1276, -29.1136)
  curve K3 (227.8202, -72.6412) -> (227.5323, -71.9239)
  line L12 (239.9904, -84.5374) -> (227.8202, -72.6412)
  curve K4 (225.8989, -60.2402) -> (239.9904, -84.5374)
  curve K5 (222.1608, -48.5975) -> (225.8989, -60.2402)
  line L13 (222.1608, 10.1316) -> (222.1608, -48.5975)
  line L14 (104.2565, 10.1316) -> (222.1608, 10.1316)
  line L15 (104.2565, -22.4542) -> (104.2565, 10.1316)
  line L16 (108.2303, -22.4542) -> (104.2565, -22.4542)
  circle C1 centre (162.3812, -25.0539) radius 2.7
  circle C2 centre (185.5706, -18.2123) radius 2.4
  circle C3 centre (185.5706, -18.2123) radius 2.4
  circle C4 centre (185.5706, -18.2123) radius 1.4
  concentric C2 C4
  dimension "d1346" diameter C4 = 2.8
extrude "Extrude168" cut sketch "Sketch166" profile of C4 against normal blind 10.5
chamfer "Chamfer79" distance 1.6
sketch "Sketch167" plane through (-19.9977, 0, 0) normal (-1, 0, 0) x axis (0, -1, 0)
  line L1 (-222.1608, 10.1316) -> (-143.2065, 10.1316)
  line L2 (-222.1608, -48.5975) -> (-222.1608, 10.1316)
  curve K1 (-222.1608, -48.5975) -> (-225.8989, -60.2402)
  curve K2 (-225.8989, -60.2402) -> (-239.9904, -84.5374)
  line L3 (-227.8202, -72.6412) -> (-239.9904, -84.5374)
  curve K3 (-227.8202, -72.6412) -> (-227.5323, -71.9239)
  line L4 (-210.1276, -29.1136) -> (-227.5323, -71.9239)
  line L5 (-143.2065, -29.1136) -> (-210.1276, -29.1136)
  line L6 (-143.2065, 10.1316) -> (-143.2065, -29.1136)
  circle C1 centre (-162.3812, -25.0539) radius 2.7
  circle C2 centre (-185.5706, -18.2123) radius 2.5
  circle C3 centre (-185.5706, -18.2123) radius 2.5
  circle C4 centre (-185.5706, -18.2123) radius 1.4
  concentric C2 C4
  dimension "d1350" diameter C4 = 2.8
extrude "Extrude169" cut sketch "Sketch167" profile of C4 against normal blind 7
chamfer "Chamfer80" distance 1.6
mirror "Mirror40" mirrorStitchTolerance 0.1
combine "Combine149"
combine "Combine150"
remove_body "RemoveBody82"
sketch "Sketch168" plane through (21.9981, 0, 0) normal (1, 0, 0) x axis (0, 1, 0)
  circle C1 centre (162.4377, -25.1855) radius 2.5
  circle C2 centre (162.4377, -25.1855) radius 3.653
  concentric C1 C2
extrude "Extrude170" add sketch "Sketch168" along normal blind 0.5
sketch "Sketch169" plane through (21.9977, 0, 0) normal (1, 0, 0) x axis (0, 1, 0)
  circle C1 centre (205, -40) radius 2.5
  circle C2 centre (205, -40) radius 3.7807
  concentric C1 C2
extrude "Extrude171" new body sketch "Sketch169" along normal blind 0.5
combine "Combine151"
remove_body "RemoveBody83"
remove_body "RemoveBody84"
mirror "Mirror41" mirrorStitchTolerance 0.1 bodies "Trigger pin 2", "5mm pin_3"
mirror "Mirror42" mirrorStitchTolerance 0.1
delete_face "DeleteFace136"
delete_face "DeleteFace137"
extrude "Extrude172" add of existing geometry blind 125.868 bodies "Prime_top Plate"
move_face "MoveFace265"
extrude "Extrude173" add of existing geometry blind 125.868 bodies "Prime_L"
move_face "MoveFace266"
extrude "Extrude174" cut of existing geometry blind -125.668
extrude "Extrude175" cut of existing geometry blind -0.25
extrude "Extrude176" cut of existing geometry blind -0.29
offset_faces "OffsetFaces27" distance 0.5
offset_faces "OffsetFaces28" distance 0.5
sketch "Sketch170" plane through (0, 27.8903, -103.6752) normal (0, -0.2598, 0.9657) x axis (1, 0, 0)
  line L1 (-12.5019, 158.3994) -> (-12.5019, 174.8073)
  line L2 (5.4981, 151.3994) -> (-5.5019, 151.3994)
  line L3 (12.4981, 174.8196) -> (12.4981, 158.3994)
  line L4 (12.4927, 174.8196) -> (12.4981, 174.8196)
  line L5 (12.4927, 199.253) -> (12.4927, 174.8196)
  line L6 (-12.5073, 199.253) -> (12.4927, 199.253)
  line L7 (-12.5073, 174.8073) -> (-12.5073, 199.253)
  line L8 (-12.5019, 174.8073) -> (-12.5073, 174.8073)
  line L9 (-9.4073, 189.8389) -> (-9.4073, 174.8196)
  line L10 (-9.0073, 190.2389) -> (-9.4073, 189.8389)
  line L11 (-9.0073, 192.253) -> (-9.0073, 190.2389)
  line L12 (4.4927, 196.753) -> (-4.5073, 196.753)
  line L13 (8.9927, 190.2389) -> (8.9927, 192.253)
  line L14 (9.3927, 189.8389) -> (8.9927, 190.2389)
  line L15 (9.3927, 174.8073) -> (9.3927, 189.8389)
  line L16 (9.3981, 174.8073) -> (9.3927, 174.8073)
  line L17 (9.3981, 161.0822) -> (9.3981, 174.8073)
  line L18 (8.9981, 160.6822) -> (9.3981, 161.0822)
  line L19 (8.9981, 158.3274) -> (8.9981, 160.6822)
  line L20 (-4.5019, 153.8274) -> (4.4981, 153.8274)
  line L21 (-9.0019, 160.6822) -> (-9.0019, 158.3274)
  line L22 (-9.4019, 161.0822) -> (-9.0019, 160.6822)
  line L23 (-9.4019, 174.8196) -> (-9.4019, 161.0822)
  line L24 (-9.4073, 174.8196) -> (-9.4019, 174.8196)
  line L25 (-9.2, 148.6467) -> (9.2, 148.6467)
  line L26 (-9.2, 201.9888) -> (-9.2, 148.6467)
  line L27 (9.2, 201.9888) -> (-9.2, 201.9888)
  line L28 (9.2, 148.6467) -> (9.2, 201.9888)
  line L29 (-9.2, 201.9888) -> (9.2, 148.6467)
  line L30 (9.2, 201.9888) -> (-9.2, 148.6467)
  line L31 (-19.1871, 138.0866) -> (19.1871, 138.0866)
  line L32 (-19.1871, 212.5489) -> (-19.1871, 138.0866)
  line L33 (19.1871, 212.5489) -> (-19.1871, 212.5489)
  line L34 (19.1871, 138.0866) -> (19.1871, 212.5489)
  line L35 (-19.1871, 212.5489) -> (19.1871, 138.0866)
  line L36 (19.1871, 212.5489) -> (-19.1871, 138.0866)
  arc A1 centre (-5.5019, 158.3994) radius 7 clockwise from (-5.5019, 151.3994) to (-12.5019, 158.3994)
  arc A2 centre (5.4981, 158.3994) radius 7 clockwise from (12.4981, 158.3994) to (5.4981, 151.3994)
  arc A3 centre (-4.5073, 192.253) radius 4.5 clockwise from (-9.0073, 192.253) to (-4.5073, 196.753)
  arc A4 centre (4.4927, 192.253) radius 4.5 clockwise from (4.4927, 196.753) to (8.9927, 192.253)
  arc A5 centre (4.4981, 158.3274) radius 4.5 clockwise from (8.9981, 158.3274) to (4.4981, 153.8274)
  arc A6 centre (-4.5019, 158.3274) radius 4.5 clockwise from (-4.5019, 153.8274) to (-9.0019, 158.3274)
  point P42 (0, 175.3177)
  point P47 (0, 175.3177)
  point P40 (-9.2, 201.9888)
  point P41 (9.2, 201.9888)
  horizontal L25
  perpendicular L25 L26
  parallel L25 L27
  parallel L26 L28
  coincident L29 P42
  coincident L30 P42
  horizontal L31
  perpendicular L31 L32
  parallel L31 L33
  parallel L32 L34
  coincident L35 P47
  coincident L36 P47
  coincident P42 P47
  dimension "d1376" distance P40 P41 = 18.4
split "Split55" bodies "Angled Mini Talon extand (1)", "Angled Mini Talon extand (2)"
remove_body "RemoveBody85"
remove_body "RemoveBody86"
fillet "Fillet175" radius 1.5
copy_paste_bodies "CopyPasteBodies12"
copy_paste_bodies "CopyPasteBodies13"
move "Move99"
move "Move100"
move "Move101"
move_face "MoveFace267"
copy_paste_bodies "CopyPasteBodies14"
move_face "MoveFace268"
sketch "Sketch171" plane through (0, 0, 0) normal (1, 0, 0) x axis (0, 1, 0)
  line L1 (218.6662, -22.9466) -> (233.7037, -9.4129)
  line L2 (218.6662, -36.3833) -> (218.6662, -22.9466)
  curve K1 (252.3821, -107.1238) -> (218.6662, -36.3833)
  line L3 (180.6935, -126.5461) -> (252.3821, -107.1238)
  line L4 (176.9575, -112.7565) -> (180.6935, -126.5461)
  line L5 (180.741, -102.825) -> (176.9575, -112.7565)
  line L6 (160.0503, -33.0679) -> (180.741, -100.6968)
  curve K2 (140.7785, -16.1797) -> (160.0503, -33.0679)
  line L7 (94.4938, -16.1797) -> (140.7785, -16.1797)
  curve K3 (61.1873, -0.0135) -> (94.4938, -16.1797)
  line L8 (207.3944, 24.9141) -> (233.7037, -9.4129)
  line L9 (61.1873, 24.9141) -> (207.3944, 24.9141)
  line L10 (61.1873, -6.8722) -> (61.1873, 24.9141)
  arc A1 centre (177.9477, -101.7609) radius 2.9891 clockwise from (180.741, -100.6968) to (180.741, -102.825)
  point P17 (61.1873, -0.0135)
  vertical L2
  perpendicular L3 L4
  tangent L5 A1
  horizontal L7
  horizontal L9
  perpendicular L9 L10
  coincident P17 L10
extrude "Extrude177" new body sketch "Sketch171" distance -12
chamfer "Chamfer81" distance 2
sketch "Sketch172" plane through (0, 61.1873, 0) normal (0, -1, 0) x axis (1, 0, 0)
  line L1 (-12, 24.9141) -> (12, 24.9141)
  line L2 (-12, -0.0135) -> (-12, 24.9141)
  line L3 (12, -0.0135) -> (-12, -0.0135)
  line L4 (12, 24.9141) -> (12, -0.0135)
  circle C1 centre (0, 12.4503) radius 7.5
  dimension "d1382" diameter C1 = 15
extrude "Extrude178" cut sketch "Sketch172" profile of C1 against normal blind 100
sketch "Sketch173" plane through (0, 0, 0) normal (1, 0, 0) x axis (0, 1, 0)
  line L1 (161.8679, 10) -> (100, 10)
  line L2 (161.8679, 15) -> (161.8679, 10)
  line L3 (100, 15) -> (161.8679, 15)
  line L4 (100, 10) -> (100, 15)
  line L5 (156.8679, 10) -> (161.8679, 10)
  line L6 (156.8679, 1.2259) -> (156.8679, 10)
  line L7 (161.8679, 1.2259) -> (156.8679, 1.2259)
  line L8 (161.8679, 10) -> (161.8679, 1.2259)
  point P2 (100, 10)
  point P5 (100, 15)
  point P3 (161.8679, 10)
  point P6 (156.8679, 10)
  horizontal L1
  vertical L2
  horizontal L3
  vertical L4
  horizontal L5
  vertical L6
  horizontal L7
  vertical L8
  dimension "d1385" distance P2 P5 = 5
  dimension "d1386" distance P3 P6 = 5
extrude "Extrude179" cut sketch "Sketch173" distance 21
move "Move102"
sketch "Sketch174" plane through (12, 0, 0) normal (1, 0, 0) x axis (0, 1, 0)
  line L1 (156.8679, 1.2259) -> (161.8679, 1.2259)
  line L2 (156.8679, 10) -> (156.8679, 1.2259)
  line L3 (100, 10) -> (156.8679, 10)
  line L4 (100, 15) -> (100, 10)
  line L5 (161.8679, 15) -> (100, 15)
  line L6 (161.8679, 1.2259) -> (161.8679, 15)
  line L7 (232.487, -7.8255) -> (232.2171, -10.7508)
  line L8 (207.3944, 24.9141) -> (232.487, -7.8255)
  line L9 (61.1873, 24.9141) -> (207.3944, 24.9141)
  line L10 (61.1873, -0.0135) -> (61.1873, 24.9141)
  curve K1 (94.4938, -16.1797) -> (61.1873, -0.0135)
  line L11 (140.7785, -16.1797) -> (94.4938, -16.1797)
  curve K2 (160.0503, -33.0679) -> (140.7785, -16.1797)
  line L12 (180.741, -100.6968) -> (160.0503, -33.0679)
  line L13 (176.9575, -112.7565) -> (180.741, -102.825)
  line L14 (180.6935, -126.5461) -> (176.9575, -112.7565)
  line L15 (252.3821, -107.1238) -> (180.6935, -126.5461)
  curve K3 (218.6662, -36.3833) -> (252.3821, -107.1238)
  line L16 (218.6662, -22.9466) -> (218.6662, -36.3833)
  line L17 (232.2171, -10.7508) -> (218.6662, -22.9466)
  arc A1 centre (177.9477, -101.7609) radius 2.9891 clockwise from (180.741, -100.6968) to (180.741, -102.825)
  circle C1 centre (80, -5) radius 4
  dimension "d1389" diameter C1 = 8
extrude "Extrude180" cut sketch "Sketch174" profile of C1 against normal blind 70
move_face "MoveFace269"
chamfer "Chamfer82" distance 2
move_face "MoveFace270"
sketch "Sketch175" plane through (0, 50.0793, -184.2919) normal (0, 0.2622, -0.965) x axis (-1, 0, 0)
  line L1 (-9.2, 161.7082) -> (-9.2, 188.0657)
  line L2 (-8.4, 160.2869) -> (-8.7607, 160.6475)
  line L3 (-8.4, 157.6869) -> (-8.4, 160.2869)
  line L4 (4.4, 153.6868) -> (-4.4, 153.6868)
  line L5 (8.4, 160.2869) -> (8.4, 157.6869)
  line L6 (8.7607, 160.6475) -> (8.4, 160.2869)
  line L7 (9.2, 188.0657) -> (9.2, 161.7082)
  line L8 (8.4, 189.4871) -> (8.7607, 189.1264)
  line L9 (8.4, 192.0871) -> (8.4, 189.4871)
  line L10 (-4.4, 196.0871) -> (4.4, 196.0871)
  line L11 (-8.4, 189.4871) -> (-8.4, 192.0871)
  line L12 (-8.7607, 189.1264) -> (-8.4, 189.4871)
  line L13 (6.75, 157.3869) -> (6.75, 192.3871)
  line L14 (-4.75, 155.3868) -> (4.75, 155.3868)
  line L15 (-6.75, 192.3871) -> (-6.75, 157.3869)
  line L16 (4.75, 194.3871) -> (-4.75, 194.3871)
  line L17 (9.566, 160.0877) -> (-9.566, 160.0877)
  line L18 (9.566, 189.7731) -> (9.566, 160.0877)
  line L19 (-9.566, 189.7731) -> (9.566, 189.7731)
  line L20 (-9.566, 160.0877) -> (-9.566, 189.7731)
  line L21 (9.566, 189.7731) -> (-9.566, 160.0877)
  line L22 (-9.566, 189.7731) -> (9.566, 160.0877)
  line L23 (8.7607, 153.3523) -> (-8.7607, 153.3523)
  line L24 (8.7607, 196.5084) -> (8.7607, 153.3523)
  line L25 (-8.7607, 196.5084) -> (8.7607, 196.5084)
  line L26 (-8.7607, 153.3523) -> (-8.7607, 196.5084)
  line L27 (8.7607, 196.5084) -> (-8.7607, 153.3523)
  line L28 (-8.7607, 196.5084) -> (8.7607, 153.3523)
  closed curve K1 centre (-7.7, 188.0657)
  closed curve K2 centre (-7.7, 161.7082)
  closed curve K3 centre (-4.4, 157.6869)
  closed curve K4 centre (4.4, 157.6869)
  closed curve K5 centre (7.7, 161.7082)
  closed curve K6 centre (7.7, 188.0657)
  closed curve K7 centre (4.4, 192.0871)
  closed curve K8 centre (-4.4, 192.0871)
  closed curve K9 centre (4.75, 157.3869)
  closed curve K10 centre (-4.75, 157.3869)
  closed curve K11 centre (-4.75, 192.3871)
  closed curve K12 centre (4.75, 192.3871)
  point P46 (0, 174.9304)
  point P51 (0, 174.9304)
  horizontal L17
  perpendicular L17 L18
  parallel L17 L19
  parallel L18 L20
  coincident L21 P46
  coincident L22 P46
  horizontal L23
  perpendicular L23 L24
  parallel L23 L25
  parallel L24 L26
  coincident L27 P51
  coincident L28 P51
  coincident P46 P51
sweep "Sweep2" sketch "Sketch175" TwistAngle 0 TaperAngle 0
move_face "MoveFace271" RotateAngle 15.1
move_face "MoveFace272"
move_face "MoveFace273"
extrude "Extrude181" cut of existing geometry blind -37.591
move_face "MoveFace274"
fillet "Fillet176" radius 1
sketch "Sketch176" plane through (0, 61.1873, 0) normal (0, -1, 0) x axis (1, 0, 0)
  line L1 (-12, 24.9141) -> (12, 24.9141)
  line L2 (-12, -0.0135) -> (-12, 24.9141)
  line L3 (12, -0.0135) -> (-12, -0.0135)
  line L4 (12, 24.9141) -> (12, -0.0135)
  line L5 (-6, 22) -> (6, 22)
  line L6 (-6, 24) -> (-6, 22)
  line L7 (6, 24) -> (-6, 24)
  line L8 (6, 22) -> (6, 24)
  line L9 (-6, 24) -> (6, 22)
  line L10 (6, 24) -> (-6, 22)
  line L11 (-4, 20.5126) -> (-4, 22)
  line L12 (4, 20.5126) -> (4, 22)
  line L13 (12, 18) -> (-12, 18)
  circle C1 centre (0, 12.4503) radius 7.5
  circle C2 centre (0, 12.4503) radius 9
  point P11 (0, 23)
  point P13 (-4, 22)
  point P14 (-4, 20.5126)
  point P15 (4, 22)
  point P16 (4, 20.5126)
  point P17 (-12, 18)
  point P18 (12, 18)
  horizontal L5
  perpendicular L5 L6
  parallel L5 L7
  parallel L6 L8
  coincident L9 P11
  coincident L10 P11
  concentric C1 C2
  coincident L5 P13
  coincident C2 P14
  perpendicular L5 L11
  coincident L5 P15
  coincident C2 P16
  perpendicular L5 L12
  coincident L2 P17
  coincident L4 P18
  perpendicular L4 L13
  dimension "d1404" diameter C2 = 18
extrude "Extrude182" cut sketch "Sketch176" profile of L1 L2 L4 L5 L6 L7 L8 C2 L11 L12 L13 against normal blind 175
fillet "Fillet177" radius 2
fillet "Fillet178" radius 2.5
move_face "MoveFace275"
fillet "Fillet179" radius 1
fillet "Fillet180" radius 1
sketch "Sketch177" plane through (-12, 0, 0) normal (-1, 0, 0) x axis (0, -1, 0)
  line L1 (-156.8679, 5.9459) -> (-156.8679, 8.2929)
  line L2 (-160.8679, 4.9459) -> (-157.8679, 4.9459)
  line L3 (-161.8679, 12.5) -> (-161.8679, 5.9459)
  line L4 (-102, 15) -> (-159.3679, 15)
  line L5 (-100, 12) -> (-100, 13)
  line L6 (-155.1608, 10) -> (-102, 10)
  line L7 (-156.575, 9) -> (-155.8679, 9.7071)
  line L8 (-212.6935, 18) -> (-61.1873, 18)
  line L9 (-232.487, -7.8255) -> (-212.6935, 18)
  line L10 (-232.2171, -10.7508) -> (-232.487, -7.8255)
  line L11 (-218.6662, -22.9466) -> (-232.2171, -10.7508)
  line L12 (-218.6662, -36.3833) -> (-218.6662, -22.9466)
  curve K1 (-252.3821, -107.1238) -> (-218.6662, -36.3833)
  line L13 (-180.6935, -126.5461) -> (-252.3821, -107.1238)
  line L14 (-176.9575, -112.7565) -> (-180.6935, -126.5461)
  line L15 (-180.741, -102.825) -> (-176.9575, -112.7565)
  line L16 (-160.0503, -33.0679) -> (-180.741, -100.6968)
  curve K2 (-140.7785, -16.1797) -> (-160.0503, -33.0679)
  line L17 (-94.4938, -16.1797) -> (-140.7785, -16.1797)
  curve K3 (-61.1873, -0.0135) -> (-94.4938, -16.1797)
  line L18 (-61.1873, 18) -> (-61.1873, -0.0135)
  line L19 (-170, -7.8255) -> (-170, 30)
  line L20 (-241.4335, -7.8255) -> (-170, -7.8255)
  line L21 (-241.4335, 31.6598) -> (-241.4335, -7.8255)
  line L22 (-170, 30) -> (-241.4335, 31.6598)
  arc A1 centre (-155.8679, 8.2929) radius 1 clockwise from (-156.8679, 8.2929) to (-156.575, 9)
  arc A2 centre (-157.8679, 5.9459) radius 1 clockwise from (-156.8679, 5.9459) to (-157.8679, 4.9459)
  arc A3 centre (-160.8679, 5.9459) radius 1 clockwise from (-160.8679, 4.9459) to (-161.8679, 5.9459)
  arc A4 centre (-159.3679, 12.5) radius 2.5 clockwise from (-161.8679, 12.5) to (-159.3679, 15)
  arc A5 centre (-102, 13) radius 2 clockwise from (-102, 15) to (-100, 13)
  arc A6 centre (-102, 12) radius 2 clockwise from (-100, 12) to (-102, 10)
  arc A7 centre (-155.1608, 9) radius 1 clockwise from (-155.8679, 9.7071) to (-155.1608, 10)
  arc A8 centre (-177.9477, -101.7609) radius 2.9891 clockwise from (-180.741, -102.825) to (-180.741, -100.6968)
  circle C1 centre (-80, -5) radius 4
  perpendicular L6 L19
  perpendicular L19 L20
  perpendicular L20 L21
split "Split56"
fillet "Fillet181" radius 2.5
chamfer "Chamfer83" distance 25.825
fillet "Fillet182" radius 0.5
fillet "Fillet183" radius 2
move_face "MoveFace276"
move_face "MoveFace277"
move_face "MoveFace278"
move_face "MoveFace279"
move_face "MoveFace280"
move_face "MoveFace281"
move_face "MoveFace282"
offset_faces "OffsetFaces29" distance 0.5
move "Move103"
move_face "MoveFace283"
fillet "Fillet184" radius 0.5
